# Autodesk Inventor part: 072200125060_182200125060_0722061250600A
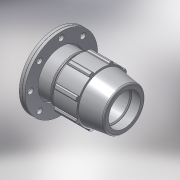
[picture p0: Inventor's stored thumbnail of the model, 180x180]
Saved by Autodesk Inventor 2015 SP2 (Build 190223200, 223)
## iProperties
Created: 2017-02
Part Number: 072200125060_182200125060_0722061250600A
Material: PVC-Piping
Description: PLASSON COMPRESSION FLANGE ADAPTOR 125-6"
Document SubType Name: Modeling
Designer: KIM
Mass: 92.6774 g
Surface Area: 199.44 cm^2
Volume: 66.1981 cm^3
Density: 1.4 g/cm^3
Appearance: Smooth - White
Author: KIM
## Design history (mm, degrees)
derived "07220.ipt"
feature "Solid1::07220.ipt"
tag "TaggingFeature1"
body "Solid1"
other parameters: "d2" = 125, "d4" = 38.57143, "d5" = 86.4, "d7" = 212, "d9" = 38.57143, "d11" = 7.71429, "d12" = 169.6, "d13" = 120 deg, "d14" = 162.5, "d15" = 8 deg, "d18" = 6.25, "d19" = 35 deg, "d20" = 17.5 deg, "d21" = 197.16, "d23" = 0, "d25" = 360 deg, "d27" = 4.24, "d42" = 94.5, "d43" = 6.36, "d46" = 3.75, "d53" = 2.5, "d67" = 10.6, "d71" = 285, "d73" = 22.5, "d74" = 90 deg, "d75" = 0.3, "d76" = 285, "d77" = 22, "d80" = 0, "d82" = 360 deg, "d85" = 180.2, "d86" = 169.6, "d87" = 1.425, "d93" = 13.5, "d95" = 112.5, "d96" = 0.3, "d99" = 360 deg, "d_" = 125, "E_" = 212, "D_" = 285, "S_" = 22
